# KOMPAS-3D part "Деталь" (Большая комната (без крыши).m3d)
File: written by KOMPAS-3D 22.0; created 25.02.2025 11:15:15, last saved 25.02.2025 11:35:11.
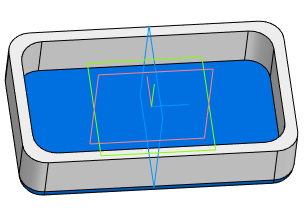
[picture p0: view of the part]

Document properties: Автор: Пользователь Windows; Полное имя файла: C:\Users\Student\Documents\Картошечка\База Сабнатика\Большая комната\Большая комната (без крыши).m3d

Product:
- Part/product: Деталь
    Масса: 0.725007

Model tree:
1. Эскиз:1
2. Элемент выдавливания:1
     Расстояние 1 = 35
3. Скругление:2  (with: Элемент выдавливания:1)
     Радиус = 10
4. Скругление:1  (with: Элемент выдавливания:1)
     Радиус = 7
5. Эскиз:3  (with: Элемент выдавливания:1)
6. Элемент выдавливания:2
     Расстояние 2 = 7
7. Эскиз:4  (with: Элемент выдавливания:2)
8. Элемент выдавливания:3
     Расстояние 2 = 21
